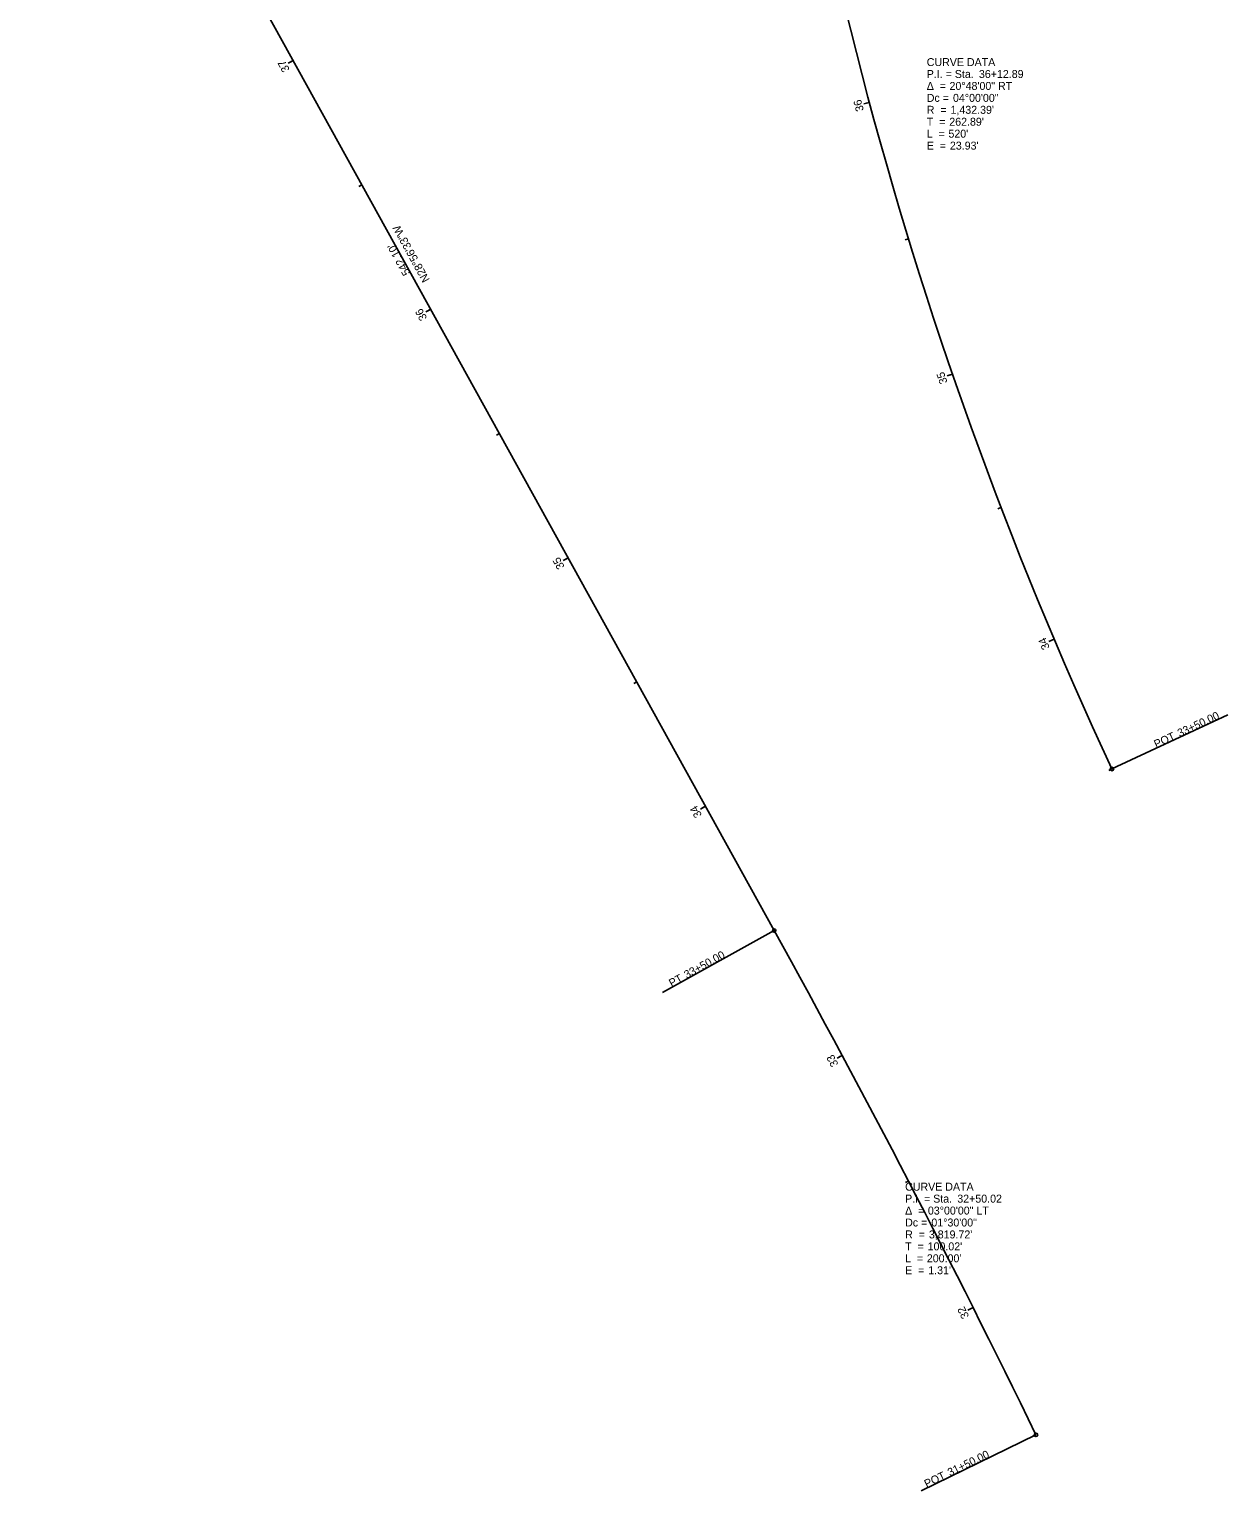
# Model space of a CAD drawing. Extents: x 1363001 to 1363920, y 487582 to 489802.
# Drawn here: x 1363498 to 1363920, y 487582 to 488097 of the extents above; entities that cross this region are included whole.
import ezdxf

# ---------------------------------------------------------------- set-up
doc = ezdxf.new("R2010")
doc.units = 0
for name, color, linetype in [('BR_X_SV_Beam_Seat', 7, 'Continuous'), ('BR_X_SV_Bottom_of_Beam_Text', 7, 'Continuous'), ('BR_X_SV_Shot_Marker', 7, 'Continuous'), ('DR_X_Cells', 7, 'Continuous'), ('DR_X_Elev_Flow', 7, 'Continuous'), ('PV_X_Curb', 7, 'Continuous'), ('RD_X_GR_Lt', 7, 'Continuous'), ('RD_X_GR_Rt', 7, 'Continuous'), ('SG_X_Interconnect_Cable', 7, 'Continuous'), ('SG_X_PullBox', 7, 'Continuous'), ('SV_P_Control_Cells_Set', 7, 'Continuous'), ('SV_X_Break_Lines', 7, 'Continuous'), ('SV_X_Shot_Marker', 7, 'Continuous'), ('SV_X_Text_Comment', 7, 'Continuous'), ('UT_X_Electric', 7, 'Continuous'), ('UT_X_Electric_Cells', 7, 'Continuous'), ('UT_X_Water', 7, 'Continuous')]:
    doc.layers.add(name, color=color, linetype=linetype)

msp = doc.modelspace()

# ---------------------------------------------------------------- linework, layer by layer
at = {"layer": 'BR_X_SV_Bottom_of_Beam_Text'}
for p, q in [((1363879.19, 487836.5), (1363919.97, 487855.53)), ((1363760.27, 487779.61), (1363720.89, 487757.83)), ((1363852.43, 487602.13), (1363811.96, 487582.45))]:
    msp.add_line(p, q, dxfattribs=at)
for centre in [(1363879.19, 487836.5), (1363760.27, 487779.61), (1363852.43, 487602.13)]:
    msp.add_circle(centre, 0.6, dxfattribs=at)
at = {"layer": 'BR_X_SV_Shot_Marker'}
for p, q in [((1363590.89, 488085.89), (1363589.14, 488084.93)), ((1363793.75, 488071.11), (1363791.82, 488070.6)), ((1363615.09, 488042.14), (1363614.04, 488041.56)), ((1363807.54, 488023.06), (1363806.39, 488022.7)), ((1363639.29, 487998.38), (1363637.54, 487997.42)), ((1363823, 487975.51), (1363821.11, 487974.86)), ((1363663.48, 487954.63), (1363662.43, 487954.05)), ((1363840.11, 487928.53), (1363838.99, 487928.1)), ((1363687.68, 487910.87), (1363685.93, 487909.9)), ((1363858.84, 487882.17), (1363857, 487881.39)), ((1363711.88, 487867.12), (1363710.83, 487866.54)), ((1363879.19, 487836.5), (1363878.1, 487835.99)), ((1363736.07, 487823.36), (1363734.32, 487822.39)), ((1363760.27, 487779.61), (1363759.22, 487779.03)), ((1363784.18, 487735.69), (1363782.42, 487734.75)), ((1363807.51, 487691.47), (1363806.45, 487690.92)), ((1363830.26, 487646.95), (1363828.48, 487646.05)), ((1363852.43, 487602.13), (1363851.35, 487601.61))]:
    msp.add_line(p, q, dxfattribs=at)
at = {"layer": 'PV_X_Curb'}
for p, q in [((1363879.19, 487836.5), (1363919.97, 487855.53)), ((1363760.27, 487779.61), (1363720.89, 487757.83)), ((1363852.43, 487602.13), (1363811.96, 487582.45))]:
    msp.add_line(p, q, dxfattribs=at)
for centre in [(1363879.19, 487836.5), (1363760.27, 487779.61), (1363852.43, 487602.13)]:
    msp.add_circle(centre, 0.6, dxfattribs=at)
at = {"layer": 'RD_X_GR_Rt'}
for p, q in [((1363823, 487975.51), (1363821.86, 487975.12)), ((1363687.68, 487910.87), (1363686.63, 487910.29))]:
    msp.add_line(p, q, dxfattribs=at)
at = {"layer": 'SG_X_PullBox'}
for p, q in [((1363590.89, 488085.89), (1363589.84, 488085.31)), ((1363793.75, 488071.11), (1363792.59, 488070.8)), ((1363639.29, 487998.38), (1363638.24, 487997.8)), ((1363823, 487975.51), (1363821.11, 487974.86)), ((1363687.68, 487910.87), (1363685.93, 487909.9)), ((1363858.84, 487882.17), (1363857.74, 487881.7)), ((1363736.07, 487823.36), (1363735.02, 487822.78)), ((1363784.18, 487735.69), (1363783.12, 487735.13)), ((1363830.26, 487646.95), (1363829.19, 487646.41))]:
    msp.add_line(p, q, dxfattribs=at)
at = {"layer": 'SV_X_Shot_Marker'}
msp.add_line((1363497.93, 488254), (1363760.27, 487779.61), dxfattribs=at)
for centre, radius, start, end in [((1365177.28, 488442.06), 1432.39, 184.20897, 205.00903), ((1360417.61, 485931.13), 3819.72, 25.94245, 28.94245)]:
    msp.add_arc(centre, radius, start, end, dxfattribs=at)
at = {"layer": 'SV_X_Text_Comment'}
msp.add_line((1363760.27, 487779.61), (1363497.93, 488254), dxfattribs=at)
for centre, radius, start, end in [((1365177.28, 488442.06), 1432.39, 184.20897, 205.00903), ((1360417.61, 485931.13), 3819.72, 25.94245, 28.94245)]:
    msp.add_arc(centre, radius, start, end, dxfattribs=at)
at = {"layer": 'UT_X_Water'}
for p, q in [((1363879.19, 487836.5), (1363919.97, 487855.53)), ((1363760.27, 487779.61), (1363720.89, 487757.83)), ((1363852.43, 487602.13), (1363811.96, 487582.45))]:
    msp.add_line(p, q, dxfattribs=at)
for centre in [(1363879.19, 487836.5), (1363760.27, 487779.61), (1363852.43, 487602.13)]:
    msp.add_circle(centre, 0.6, dxfattribs=at)

# ---------------------------------------------------------------- texts
at = {"layer": 'BR_X_SV_Beam_Seat'}
msp.add_text('N28°56\'33"W', height=2.8, rotation=118.9424, dxfattribs=at).set_placement((1363639.04, 488008.74))
at = {"layer": 'BR_X_SV_Bottom_of_Beam_Text'}
for s, rotation, p in [('33+50.00', 25.009, (1363903.03, 487847.68)), ('POT', 25.009, (1363894.76, 487843.82)), ('33+50.00', 28.9424, (1363729.46, 487762.62)), ('PT', 28.9424, (1363724.13, 487759.68)), ('31+50.00', 25.9424, (1363822.14, 487587.45)), ('POT', 25.9424, (1363813.93, 487583.45))]:
    msp.add_text(s, height=2.8, rotation=rotation, dxfattribs=at).set_placement(p)
at = {"layer": 'BR_X_SV_Shot_Marker'}
for s, rotation, p in [('37', 118.9424, (1363589.75, 488082.69)), ('36', 105.009, (1363791.86, 488068.33)), ('36', 118.9424, (1363638.12, 487995.23)), ('35', 109.009, (1363821.31, 487972.59)), ('35', 118.9424, (1363686.52, 487907.71)), ('34', 113.009, (1363857.34, 487879.2)), ('34', 118.9424, (1363734.88, 487820.25)), ('33', 118.1924, (1363782.96, 487732.57)), ('32', 116.6924, (1363828.97, 487643.85))]:
    msp.add_text(s, height=2.8, rotation=rotation, dxfattribs=at).set_placement(p)
at = {"layer": 'DR_X_Cells'}
msp.add_text("542.10'", height=2.8, rotation=118.9424, dxfattribs=at).set_placement((1363632.2, 488011.11))
at = {"layer": 'DR_X_Elev_Flow'}
for s, p in [('CURVE DATA', (1363813.97, 488083.92)), ('P.I. = Sta. ', (1363813.97, 488079.72)), ('36+12.89', (1363832.34, 488079.72)), ('Δ  = ', (1363813.97, 488075.52)), ('20°48\'00" RT', (1363821.99, 488075.52)), ('Dc = ', (1363813.97, 488071.32)), ('04°00\'00"', (1363823.21, 488071.32)), ('R  = ', (1363813.97, 488067.12)), ("1,432.39'", (1363822.34, 488067.12)), ('T  = ', (1363813.97, 488062.92)), ('L  = ', (1363813.97, 488058.72)), ("520'", (1363821.61, 488058.72)), ("262.89'", (1363821.9, 488062.92)), ('E  = ', (1363813.97, 488054.52)), ("23.93'", (1363822.12, 488054.52)), ('CURVE DATA', (1363806.35, 487688.07)), ('P.I. = Sta. ', (1363806.35, 487683.87)), ('32+50.02', (1363824.72, 487683.87)), ('Δ  = ', (1363806.35, 487679.67)), ('03°00\'00" LT', (1363814.37, 487679.67)), ('Dc = ', (1363806.35, 487675.47)), ('01°30\'00"', (1363815.59, 487675.47)), ('R  = ', (1363806.35, 487671.27)), ("3,819.72'", (1363814.72, 487671.27)), ('T  = ', (1363806.35, 487667.07)), ('L  = ', (1363806.35, 487662.87)), ("200.00'", (1363814, 487662.87)), ("100.02'", (1363814.28, 487667.07)), ('E  = ', (1363806.35, 487658.67)), ("1.31'", (1363814.5, 487658.67))]:
    msp.add_text(s, height=2.8, dxfattribs=at).set_placement(p)
at = {"layer": 'PV_X_Curb'}
for s, rotation, p in [('33+50.00', 25.009, (1363903.03, 487847.68)), ('POT', 25.009, (1363894.76, 487843.82)), ('33+50.00', 28.9424, (1363729.46, 487762.62)), ('PT', 28.9424, (1363724.13, 487759.68)), ('31+50.00', 25.9424, (1363822.14, 487587.45)), ('POT', 25.9424, (1363813.93, 487583.45))]:
    msp.add_text(s, height=2.8, rotation=rotation, dxfattribs=at).set_placement(p)
at = {"layer": 'RD_X_GR_Lt'}
msp.add_text("542.10'", height=2.8, rotation=118.9424, dxfattribs=at).set_placement((1363632.2, 488011.11))
at = {"layer": 'SG_X_Interconnect_Cable'}
msp.add_text('N28°56\'33"W', height=2.8, rotation=118.9424, dxfattribs=at).set_placement((1363639.04, 488008.74))
at = {"layer": 'SG_X_PullBox'}
for rotation, p in [(109.009, (1363821.31, 487972.59)), (118.9424, (1363686.52, 487907.71))]:
    msp.add_text('35', height=2.8, rotation=rotation, dxfattribs=at).set_placement(p)
at = {"layer": 'SV_P_Control_Cells_Set'}
for s, p in [('CURVE DATA', (1363813.97, 488083.92)), ('P.I. = Sta. ', (1363813.97, 488079.72)), ('36+12.89', (1363832.34, 488079.72)), ('Δ  = ', (1363813.97, 488075.52)), ('20°48\'00" RT', (1363821.99, 488075.52)), ('Dc = ', (1363813.97, 488071.32)), ('04°00\'00"', (1363823.21, 488071.32)), ('R  = ', (1363813.97, 488067.12)), ("1,432.39'", (1363822.34, 488067.12)), ('T  = ', (1363813.97, 488062.92)), ('L  = ', (1363813.97, 488058.72)), ("520'", (1363821.61, 488058.72)), ("262.89'", (1363821.9, 488062.92)), ('E  = ', (1363813.97, 488054.52)), ("23.93'", (1363822.12, 488054.52)), ('CURVE DATA', (1363806.35, 487688.07)), ('P.I. = Sta. ', (1363806.35, 487683.87)), ('32+50.02', (1363824.72, 487683.87)), ('Δ  = ', (1363806.35, 487679.67)), ('03°00\'00" LT', (1363814.37, 487679.67)), ('Dc = ', (1363806.35, 487675.47)), ('01°30\'00"', (1363815.59, 487675.47)), ('R  = ', (1363806.35, 487671.27)), ("3,819.72'", (1363814.72, 487671.27)), ('T  = ', (1363806.35, 487667.07)), ('L  = ', (1363806.35, 487662.87)), ("200.00'", (1363814, 487662.87)), ("100.02'", (1363814.28, 487667.07)), ('E  = ', (1363806.35, 487658.67)), ("1.31'", (1363814.5, 487658.67))]:
    msp.add_text(s, height=2.8, dxfattribs=at).set_placement(p)
at = {"layer": 'SV_X_Break_Lines'}
msp.add_text("542.10'", height=2.8, rotation=118.9424, dxfattribs=at).set_placement((1363632.2, 488011.11))
at = {"layer": 'UT_X_Electric'}
for s, p in [('CURVE DATA', (1363813.97, 488083.92)), ('P.I. = Sta. ', (1363813.97, 488079.72)), ('36+12.89', (1363832.34, 488079.72)), ('Δ  = ', (1363813.97, 488075.52)), ('20°48\'00" RT', (1363821.99, 488075.52)), ('Dc = ', (1363813.97, 488071.32)), ('04°00\'00"', (1363823.21, 488071.32)), ('R  = ', (1363813.97, 488067.12)), ("1,432.39'", (1363822.34, 488067.12)), ('T  = ', (1363813.97, 488062.92)), ('L  = ', (1363813.97, 488058.72)), ("520'", (1363821.61, 488058.72)), ("262.89'", (1363821.9, 488062.92)), ('E  = ', (1363813.97, 488054.52)), ("23.93'", (1363822.12, 488054.52)), ('CURVE DATA', (1363806.35, 487688.07)), ('P.I. = Sta. ', (1363806.35, 487683.87)), ('32+50.02', (1363824.72, 487683.87)), ('Δ  = ', (1363806.35, 487679.67)), ('03°00\'00" LT', (1363814.37, 487679.67)), ('Dc = ', (1363806.35, 487675.47)), ('01°30\'00"', (1363815.59, 487675.47)), ('R  = ', (1363806.35, 487671.27)), ("3,819.72'", (1363814.72, 487671.27)), ('T  = ', (1363806.35, 487667.07)), ('L  = ', (1363806.35, 487662.87)), ("200.00'", (1363814, 487662.87)), ("100.02'", (1363814.28, 487667.07)), ('E  = ', (1363806.35, 487658.67)), ("1.31'", (1363814.5, 487658.67))]:
    msp.add_text(s, height=2.8, dxfattribs=at).set_placement(p)
at = {"layer": 'UT_X_Electric_Cells'}
msp.add_text('N28°56\'33"W', height=2.8, rotation=118.9424, dxfattribs=at).set_placement((1363639.04, 488008.74))
at = {"layer": 'UT_X_Water'}
for s, rotation, p in [('33+50.00', 25.009, (1363903.03, 487847.68)), ('POT', 25.009, (1363894.76, 487843.82)), ('33+50.00', 28.9424, (1363729.46, 487762.62)), ('PT', 28.9424, (1363724.13, 487759.68)), ('31+50.00', 25.9424, (1363822.14, 487587.45)), ('POT', 25.9424, (1363813.93, 487583.45))]:
    msp.add_text(s, height=2.8, rotation=rotation, dxfattribs=at).set_placement(p)

doc.saveas('drawing.dxf')
